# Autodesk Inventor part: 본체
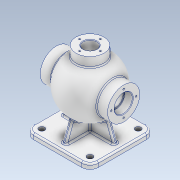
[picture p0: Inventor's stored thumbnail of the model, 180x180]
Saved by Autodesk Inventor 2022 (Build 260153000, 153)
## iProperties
Created: 2024-04
Part Number: 본체
Material: 알루미늄 6061
Document SubType Name: Modeling
Designer: admin
Density: 2.7 g/cm^3
Appearance: 알루미늄 - 평지
Mass: 1526.73 g
Surface Area: 1173.98 cm^2
Volume: 565.456 cm^3
Author: admin
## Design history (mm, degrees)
sketch "스케치1"
  geometry: L1 (-91, 0)-(91, 0) reference; L2 (-65, 31)-(65, 31); L3 (65, 31)-(65, 0); L4 (-65, 0)-(-65, 31); L5 (-65, 0)-(65, 0); L6 (0, -10.8)-(0, 64.8) reference; A1 r 54 centre (0, 0) between (54, 0) and (-54, 0); 4 further points
  constraints: 8 end point, 3 point on line, 2 point on circle, 1 centre point, 1 coincident, 1 horizontal, 1 parallel, 1 perpendicular, 1 symmetric about line
  dimensions: "d3" = 54 radius of A1; "d5" = 130 distance of L2.start L2.end; "d6" = 31 distance of L2.end L3.end
revolve "회전1" sketch "스케치1" stored, may be unused: angle "d7" = 90 deg
sketch "스케치2"
  geometry: 1 further point
node "작업 평면1"
sketch "스케치3"
  geometry: C1 r 27 at (0, 0); 1 further point
  constraints: 1 centre point, 1 coincident
  dimensions: "d9" = 54 diameter of C1
extrude "돌출1" join sketch "스케치3" stored distance "d10" = 10; taper "d11" = 0 deg
node "작업 평면2"
sketch "스케치4"
  geometry: L1 (46.5, -62.5)-(-46.5, -62.5); L2 (-62.5, -46.5)-(-62.5, 46.5); L3 (-46.5, 62.5)-(46.5, 62.5); L4 (62.5, 46.5)-(62.5, -46.5); L5 (62.5, -62.5)-(-62.5, 62.5); L6 (-62.5, -62.5)-(62.5, 62.5); A1 r 16 centre (46.5, -46.5) between (46.5, -62.5) and (62.5, -46.5); A2 r 16 centre (46.5, 46.5) between (62.5, 46.5) and (46.5, 62.5); A3 r 16 centre (-46.5, 46.5) between (-46.5, 62.5) and (-62.5, 46.5); A4 r 16 centre (-46.5, -46.5) between (-62.5, -46.5) and (-46.5, -62.5); 1 further point
  constraints: 12 end point, 8 point on circle, 8 point on line, 8 tangent, 4 centre point, 3 equal radius, 2 midpoint, 2 parallel, 1 horizontal, 1 perpendicular
  dimensions: "d13" = 125 distance of L5.start L6.start; "d14" = 125 distance of L6.start L5.end; "d15" = 16 radius of A1
extrude "돌출2" join sketch "스케치4" distance "d16" = 10; taper "d17" = 0 deg
sketch "스케치5"
  geometry: L1 (-23.202, 0)-(23.202, 0); L2 (23.202, 0)-(50.5, -75); L3 (50.5, -75)-(-50.5, -75); L4 (46.5, -75)-(-46.5, -75) reference; L5 (-23.202, 0)-(-50.5, -75); L6 (0, -115)-(0, 95) reference; L7 (-91, 0)-(91, 0) reference; L8 (-62.5, -85)-(-62.5, -75) reference; 1 further point
  constraints: 8 end point, 2 symmetric about line, 1 horizontal, 1 midpoint, 1 point on line
  dimensions: "d18" = 12 distance from line of L3.end L8; "d19" = 20 deg angle of L5 L8
extrude "돌출3" join sketch "스케치5" stored distance "d20" = 8; taper "d21" = 0 deg
fillet "모깎기1" dims "d22" = 3
sketch "스케치6"
  geometry: L1 (-91, 0)-(91, 0) reference; L2 (0, -115)-(0, 95) reference; L3 (-65, -31)-(-65, 31) reference; L4 (-65, 0)-(-49, 0); L5 (-49, 0)-(-49, 16.9); L6 (-49.6, 17.5)-(-65, 17.5); L7 (-65, 17.5)-(-65, 0); L8 (-49, 0)-(-41.364, 0); L9 (-41.364, 0)-(-41.364, 15); L10 (-41.364, 15)-(-49, 15); L11 (-49, 15)-(-49, 0); L12 (41.364, 0)-(49, 0); L13 (49, 0)-(49, 15); L14 (49, 15)-(41.364, 15); L15 (41.364, 15)-(41.364, 0); L16 (65, -31)-(65, 31) reference; L17 (65, 0)-(49, 0); L18 (49, 0)-(49, 16.9); L19 (49.6, 17.5)-(65, 17.5); L20 (65, 17.5)-(65, 0); L21 (-41.364, 0)-(41.364, 0); A1 r 44 centre (0, 0) between (44, 0) and (-44, 0); A2 r 0.6 centre (49.6, 16.9) between (49.6, 17.5) and (49, 16.9); A3 r 0.6 centre (-49.6, 16.9) between (-49, 16.9) and (-49.6, 17.5); 13 further points
  constraints: 34 end point, 8 parallel, 8 point on circle, 8 point on line, 4 horizontal, 4 perpendicular, 4 tangent, 3 centre point, 2 midpoint, 1 coincident, 1 collinear, 1 equal radius
  dimensions: "d26" = 88 diameter of A1; "d27" = 16 distance of point (-49, 17.5) L6.end; "d28" = 16 distance of point (49, 17.5) L19.end; "d29" = 30 diameter of L14 L1; "d30" = 30 diameter of L10 L1; "d31" = 35 diameter of L19 L1; "d32" = 35 diameter of L6 L1; "d82" = 0.6 radius of A2
revolve "회전2" sketch "스케치6" stored, may be unused: angle "d33" = 90 deg
sketch "스케치7"
  geometry: C1 r 27 at (0, 0) reference; 2 further points
  constraints: 1 coincident
hole "구멍1" sketch "스케치7" at (0, 0) diameter "d34" = 26; stored, may be unused: countersink angle "d38" = 90 deg, drill point angle "d40" = 0 deg; dims "d35" = 8, "d36" = 4, "d37" = 2, "d39" = 11.8
chamfer "모따기1" distance "d41" = 1; stored, may be unused: second distance "d42" = 2, angle "d43" = 45 deg
sketch "스케치8"
  geometry: 2 further points
  constraints: 1 vertical alignment
  dimensions: "d51" = 24 distance of point (0, 0) point (0, 24)
hole "구멍2" sketch "스케치8" at (0, 24) diameter "d44" = 3.242; stored, may be unused: countersink angle "d48" = 90 deg, drill point angle "d50" = 118 deg; dims "d45" = 12, "d46" = 4, "d47" = 2, "d49" = 15
sketch "스케치9"
  geometry: C1 r 1.621 at (0, 24) reference; 2 further points
  constraints: 1 coincident
hole "구멍3" sketch "스케치9" at (0, 24) diameter "d52" = 3.242; stored, may be unused: countersink angle "d56" = 90 deg, drill point angle "d58" = 118 deg; dims "d53" = 12, "d54" = 4, "d55" = 2, "d57" = 15
chamfer "모따기2" distance "d62" = 1; stored, may be unused: second distance "d63" = 2, angle "d64" = 45 deg
fillet "모깎기2" dims "d65" = 3
fillet "모깎기3" dims "d66" = 3
sketch "스케치10"
  geometry: A1 r 16 centre (46.5, -46.5) between (46.5, -62.5) and (62.5, -46.5) reference; A2 r 16 centre (-46.5, -46.5) between (-62.5, -46.5) and (-46.5, -62.5) reference; A3 r 16 centre (46.5, 46.5) between (62.5, 46.5) and (46.5, 62.5) reference; A4 r 16 centre (-46.5, 46.5) between (-46.5, 62.5) and (-62.5, 46.5) reference; 5 further points
  constraints: 4 coincident
hole "구멍4" sketch "스케치10" at (46.5, -46.5), (-46.5, -46.5), (46.5, 46.5), (-46.5, 46.5) diameter "d67" = 11; stored, may be unused: countersink angle "d71" = 90 deg, drill point angle "d73" = 118 deg; dims "d68" = 12, "d69" = 4, "d70" = 2, "d72" = 15
sketch "스케치11"
  geometry: A1 r 20 centre (0, 0) between (0, -20) and (-20, 0); 3 further points
  constraints: 4 point on circle, 1 centre point, 1 coincident, 1 vertical alignment
  dimensions: "d81" = 20 distance of point (0, 0) A1.start
hole "구멍5" sketch "스케치11" at (0, -20), (-20, 0), (0, 20), (20, 0) diameter "d74" = 3.242; stored, may be unused: countersink angle "d78" = 90 deg, drill point angle "d80" = 118 deg; dims "d75" = 9, "d76" = 4, "d77" = 2, "d79" = 11
fillet "모깎기4" dims "d83" = 3
node "작업 평면3"
sketch "스케치12"
  geometry: L1 (27, 65)-(-27, 65) reference; 2 further points
  constraints: 1 vertical alignment, 1 other
  dimensions: "d85" = 9 distance from line of L1 point (0, 56)
feature "엠보싱1" sketch "스케치12" dims "d3" = 54, "d5" = 130, "d6" = 31, "d13" = 125, "d14" = 125, "d15" = 16, "d86" = 0.5, "d87" = 0
node "솔리드1"
pattern_circular "원형 패턴1" dims angle "d24" = 90 deg
pattern_circular "원형 패턴2" dims angle "d60" = 360 deg
feature "A9D066F2-1C7D-4E18-AEED-F7BC21143FA4" dims "d44" = 3.242, "d45" = 12, "d46" = 4, "d47" = 2, "d48" = 90 deg, "d49" = 15, "d50" = 118 deg
other parameters: "d0" = 108, "d8" = 65, "d12" = -85, "d84" = -36
